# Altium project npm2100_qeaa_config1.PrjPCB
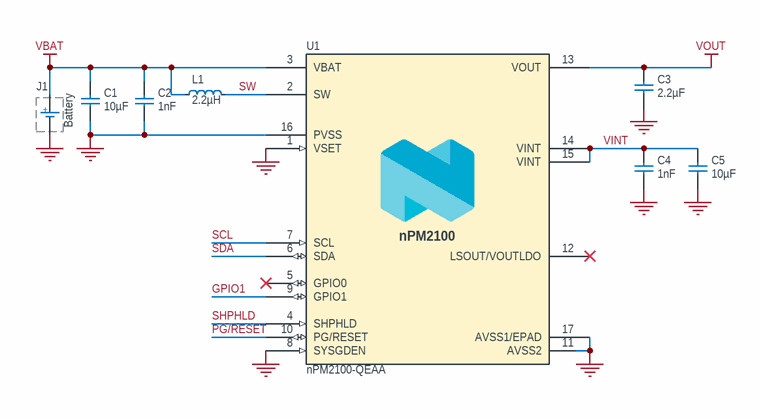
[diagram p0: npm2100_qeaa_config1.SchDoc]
1 sheet, 8 parts. Net scope: global (net labels, ports and power ports of the same name join across sheets).
Board file: npm2100_qeaa_config1.PcbDoc

## Sheet npm2100_qeaa_config1.SchDoc: nPM2100-QxAA Ref. Layout Config. 1
size A4; Revision: 0.2; SheetNumber: 1; SheetTotal: 1; DrawnBy: DABA; DocumentSize: A4; BoardTitle: nPM2100-QxAA Ref. Layout Config. 1; PCAName: nPM2100-QEAA; RefLayoutTitle: Reference Layout Config. 1: Simple; Device: nPM2100-QEAA; Classification: Public

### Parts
C1  10µF  [CAPC1005X04L_C2]
C2  1nF  [CAPC0603X03L_C]
C3  2.2µF  [CAPC1005X04L_C2]
C4  1nF  [CAPC0603X03L_C]
C5  10µF  [CAPC1005X04L_C2]
J1  Battery  [TP_2x1mm_TH]  (graphical)
L1  2.2µH  [INDC1608X06L_C2]
U1  nPM2100-QEAA  [QFN65P400X400X65_HS-17N]

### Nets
GND: C1.1 C2.1 C3.1 C4.1 C5.1 J1.1(GND) U1.1(VSET) U1.8(SYSGDEN) U1.11(AVSS2) U1.16(PVSS) U1.17(AVSS1/EPAD)
VBAT: C1.2 C2.2 J1.2(V+) L1.1 U1.3(VBAT)
VOUT: C3.2 U1.13(VOUT)
GPIO1: U1.9(GPIO1)
PG/RESET: U1.10(PG/RESET)
SCL: U1.7(SCL)
SDA: U1.6(SDA)
SHPHLD: U1.4(SHPHLD)
SW: L1.2 U1.2(SW)
VINT: C4.2 C5.2 U1.14(VINT) U1.15(VINT)

Not connected (* = marked no-connect by the designer): U1 5(GPIO0)* 12(LSOUT/VOUTLDO)*

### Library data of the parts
C1 C5 = C0402-10µ-6.3V-X5R-GRM155R60J106ME05D: Capacitor, X5R, ±20%, 6.3V; Manufacturer: Murata; Part number NEMS: 100200554; Component Status: Active; Pad Count: 2; Artikkelnr Noca: N.A.
C2 C4 = C0201-1n0-50V-X7R: Capacitor, X7R, ±10pF, 50V; Manufacturer: Murata; Manufacturer Part Number: GRM033R71H102KA12D; Part number NEMS: 100200404; Component Status: Active; Pad Count: 2; Artikkelnr Noca: N.A.
C3 = C0402-2µ2-6.3V-X5R-GRM155R60J225ME01D: Capacitor, X5R, ±20%, 6.3V; Manufacturer: Murata; Part number NEMS: 100200557; Component Status: Active; Pad Count: 2; Artikkelnr Noca: N.A.
J1 = Battery_TP: Manufacturer: N.A.; Part number NEMS: 101800006; Component Status: Active; Pad Count: 3
L1 = L0603-2µ2-1.8A-237mOhm-LSCNB1608HKT2R2MD: Unshielded Multilayer Inductor, 1.2A, ±20%, 137.5mOhm; Manufacturer: Taiyo Yuden; Part number NEMS: 100300450; Component Status: Active; Pad Count: 2; Note: -40°C ~ 125°C; Artikkelnr Noca: N.A.
U1 = nPM2100-QEAA: Boost converter companion PMIC for maximum energy extraction of primary (no-rechargeable) batteries; Manufacturer: Nordic Semiconductor; Part number NEMS: 102000298; Component Status: Active; Pad Count: 17; Note: N.A.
